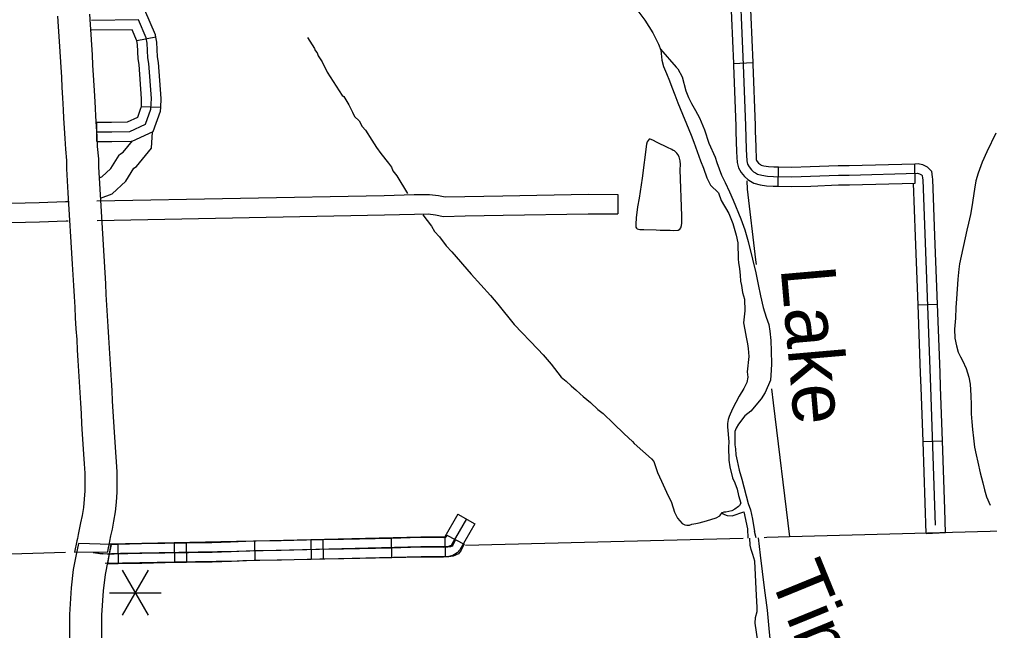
# Model space of a CAD drawing. Extents: x -117616 to 64730, y 54117 to 789866.
# Drawn here: x 62435.1 to 62585, y 55033 to 55127.3 of the extents above; entities that cross this region are included whole.
import ezdxf

# ---------------------------------------------------------------- set-up
doc = ezdxf.new("R2010")
doc.units = 0
for name, color, linetype in [('10', 7, 'Continuous'), ('2', 7, 'Continuous'), ('32', 7, 'Continuous'), ('35', 7, 'Continuous'), ('48', 7, 'Continuous'), ('Level 10', 7, 'Continuous'), ('Level 2', 7, 'Continuous'), ('Level 32', 7, 'Continuous'), ('Level 35', 7, 'Continuous'), ('Level 45', 7, 'Continuous'), ('Level 46', 7, 'Continuous'), ('Level 5', 7, 'Continuous')]:
    doc.layers.add(name, color=color, linetype=linetype)

msp = doc.modelspace()

# ---------------------------------------------------------------- linework, layer by layer
at = {"layer": '10'}
for points in [[(62444.23, 55046.37), (62443.89, 55044.71), (62443.44, 55042.37), (62443.12, 55039.56), (62442.84, 55035.45), (62442.87, 55033.31), (62442.86, 55030.92), (62443.07, 55026.85), (62443.12, 55024.64)], [(62448.12, 55024.76), (62448.06, 55027.03), (62447.86, 55031.04), (62447.87, 55033.33), (62447.84, 55035.32), (62448.1, 55039.1), (62448.39, 55041.61), (62448.8, 55043.74), (62449.28, 55046.24), (62444.23, 55046.37)]]:
    msp.add_lwpolyline(points, dxfattribs=at)
at = {"layer": '2'}
for points in [[(62654.83, 55050.09), (62554.1, 55047.4), (62550.56, 55047.3), (62550.19, 55047.29)], [(62546.95, 55047.18), (62504.02, 55046.07)]]:
    msp.add_lwpolyline(points, dxfattribs=at)
at = {"layer": '32'}
for p, q in [((62492.53, 55047.18), (62492.59, 55044.18)), ((62501.17, 55047.67), (62503.84, 55046.3)), ((62450.3, 55046.25), (62450.37, 55043.25)), ((62460.87, 55046.45), (62460.92, 55043.45)), ((62471.43, 55046.77), (62471.47, 55043.77)), ((62481.97, 55046.97), (62482.04, 55043.97))]:
    msp.add_line(p, q, dxfattribs=at)
for points in [[(62492.53, 55047.18), (62485.16, 55047.03), (62481.97, 55046.97)], [(62501.17, 55047.67), (62500.98, 55047.3), (62500.58, 55047.29), (62496.97, 55047.31), (62492.56, 55047.18), (62492.53, 55047.18)], [(62502.51, 55046.98), (62502.07, 55046.14), (62501.97, 55046), (62501.69, 55045.89), (62501.29, 55045.81), (62500.6, 55045.79), (62496.98, 55045.81), (62492.59, 55045.68), (62485.19, 55045.53), (62481.47, 55045.46), (62475.57, 55045.32), (62471.33, 55045.26), (62467.81, 55045.1), (62464.87, 55045.02), (62457.6, 55044.9), (62454.02, 55044.83), (62449.77, 55044.74), (62448.69, 55044.74), (62448.06, 55044.78), (62447.45, 55044.83), (62446.49, 55044.96)], [(62450.3, 55046.25), (62449.76, 55046.24), (62449.28, 55046.24), (62448.95, 55044.51), (62448.7, 55043.24)], [(62460.87, 55046.45), (62457.58, 55046.4), (62453.99, 55046.33), (62450.3, 55046.25)], [(62471.43, 55046.77), (62471.29, 55046.76), (62467.75, 55046.6), (62464.84, 55046.52), (62460.87, 55046.45)], [(62481.97, 55046.97), (62481.44, 55046.96), (62475.54, 55046.82), (62471.43, 55046.77)], [(62503.84, 55046.3), (62503.36, 55045.35), (62502.94, 55044.78), (62502.12, 55044.44), (62501.45, 55044.32), (62500.62, 55044.29), (62497, 55044.31), (62492.63, 55044.19), (62492.59, 55044.18)], [(62492.59, 55044.18), (62485.22, 55044.03), (62482.04, 55043.97)], [(62450.37, 55043.25), (62449.79, 55043.24), (62448.7, 55043.24)], [(62460.92, 55043.45), (62457.63, 55043.4), (62454.04, 55043.33), (62450.37, 55043.25)], [(62471.47, 55043.77), (62471.38, 55043.77), (62467.86, 55043.6), (62464.9, 55043.52), (62460.92, 55043.45)], [(62482.04, 55043.97), (62481.51, 55043.96), (62475.6, 55043.82), (62471.47, 55043.77)]]:
    msp.add_lwpolyline(points, dxfattribs=at)
at = {"layer": '35'}
for points in [[(62549.17, 55031.34), (62548.79, 55034.08), (62548.83, 55034.96), (62549.1, 55035.88), (62549.1, 55036.55), (62549, 55038.35), (62548.73, 55043.65), (62548.41, 55044.69), (62548.16, 55045.47), (62548, 55046.12), (62547.97, 55047.21)], [(62549.25, 55047.27), (62549.56, 55044.59), (62550.15, 55039.53), (62550.65, 55036.1), (62550.91, 55033.25), (62551.15, 55030.67)]]:
    msp.add_lwpolyline(points, dxfattribs=at)
at = {"layer": '48'}
for p, q in [((62455.01, 55042.26), (62451.01, 55035.34)), ((62451.01, 55042.26), (62455.01, 55035.34)), ((62449.01, 55038.8), (62457.01, 55038.8))]:
    msp.add_line(p, q, dxfattribs=at)
at = {"layer": 'Level 10'}
for p, q in [((62446.09, 55126.54), (62445.99, 55128.11)), ((62441, 55127.81), (62441.1, 55126.23)), ((62441.1, 55126.23), (62441.2, 55124.66)), ((62446.19, 55124.98), (62446.09, 55126.54)), ((62441.2, 55124.66), (62441.3, 55123.1)), ((62446.29, 55123.4), (62446.19, 55124.98)), ((62441.3, 55123.1), (62441.39, 55121.52)), ((62446.38, 55121.82), (62446.29, 55123.4)), ((62441.39, 55121.52), (62441.49, 55119.93)), ((62446.48, 55120.25), (62446.38, 55121.82)), ((62441.49, 55119.93), (62441.59, 55118.36)), ((62446.58, 55118.67), (62446.48, 55120.25)), ((62441.59, 55118.36), (62441.68, 55116.79)), ((62446.67, 55117.08), (62446.58, 55118.67)), ((62441.68, 55116.79), (62441.77, 55115.21)), ((62446.77, 55115.5), (62446.67, 55117.08)), ((62441.77, 55115.21), (62441.88, 55113.33)), ((62446.87, 55113.6), (62446.77, 55115.5)), ((62441.88, 55113.33), (62441.95, 55112.07)), ((62446.94, 55112.34), (62446.87, 55113.6)), ((62441.95, 55112.07), (62442.03, 55110.49)), ((62447.03, 55110.77), (62446.94, 55112.34)), ((62442.03, 55110.49), (62442.12, 55108.92)), ((62447.12, 55109.2), (62447.03, 55110.77)), ((62442.12, 55108.92), (62442.21, 55107.29)), ((62447.2, 55107.67), (62447.12, 55109.2)), ((62442.21, 55107.29), (62442.38, 55105.53)), ((62447.38, 55105.77), (62447.2, 55107.67)), ((62447.38, 55104.53), (62447.38, 55105.77)), ((62442.38, 55105.53), (62442.38, 55104.22)), ((62442.38, 55104.22), (62442.58, 55100.55)), ((62448.44, 55086.49), (62447.38, 55104.53)), ((62442.58, 55100.55), (62443.26, 55089.53)), ((62443.26, 55089.53), (62443.35, 55087.87)), ((62443.35, 55087.87), (62443.45, 55086.2)), ((62443.45, 55086.2), (62443.55, 55084.54)), ((62448.54, 55084.83), (62448.44, 55086.49)), ((62448.64, 55083.18), (62448.54, 55084.83)), ((62443.55, 55084.54), (62443.65, 55082.88)), ((62448.74, 55081.52), (62448.64, 55083.18)), ((62443.65, 55082.88), (62443.75, 55081.21)), ((62443.75, 55081.21), (62443.85, 55079.55)), ((62448.84, 55079.87), (62448.74, 55081.52)), ((62443.85, 55079.55), (62443.96, 55077.91)), ((62448.95, 55078.21), (62448.84, 55079.87)), ((62443.96, 55077.91), (62444.06, 55076.26)), ((62449.05, 55076.55), (62448.95, 55078.21)), ((62444.06, 55076.26), (62444.15, 55074.62)), ((62449.14, 55074.9), (62449.05, 55076.55)), ((62444.15, 55074.62), (62444.24, 55072.98)), ((62449.23, 55073.25), (62449.14, 55074.9)), ((62444.24, 55072.98), (62444.33, 55071.34)), ((62449.32, 55071.62), (62449.23, 55073.25)), ((62444.33, 55071.34), (62444.43, 55069.7)), ((62449.42, 55070.01), (62449.32, 55071.62)), ((62444.43, 55069.7), (62444.53, 55068.08)), ((62449.52, 55068.39), (62449.42, 55070.01)), ((62449.62, 55066.78), (62449.52, 55068.39)), ((62444.53, 55068.08), (62444.63, 55066.47)), ((62449.72, 55065.17), (62449.62, 55066.78)), ((62444.63, 55066.47), (62444.73, 55064.87)), ((62449.81, 55063.59), (62449.72, 55065.17)), ((62444.73, 55064.87), (62444.82, 55063.29)), ((62444.82, 55063.29), (62444.92, 55061.72)), ((62449.91, 55062.03), (62449.81, 55063.59)), ((62444.92, 55061.72), (62445.02, 55060.18)), ((62450.01, 55060.5), (62449.91, 55062.03)), ((62445.02, 55060.18), (62445.11, 55058.68)), ((62450.1, 55058.98), (62450.01, 55060.5)), ((62445.11, 55058.68), (62445.2, 55057.23)), ((62450.19, 55057.45), (62450.1, 55058.98)), ((62445.2, 55057.23), (62445.24, 55055.85)), ((62450.24, 55055.89), (62450.19, 55057.45)), ((62445.24, 55055.85), (62445.22, 55054.52)), ((62450.22, 55054.33), (62450.24, 55055.89)), ((62445.14, 55053.23), (62444.99, 55051.97)), ((62445.22, 55054.52), (62445.14, 55053.23)), ((62450.12, 55052.78), (62450.22, 55054.33)), ((62444.99, 55051.97), (62444.79, 55050.74)), ((62449.94, 55051.28), (62450.12, 55052.78)), ((62444.79, 55050.74), (62444.57, 55049.59)), ((62449.71, 55049.86), (62449.94, 55051.28)), ((62444.57, 55049.59), (62444.36, 55048.58)), ((62449.47, 55048.62), (62449.71, 55049.86)), ((62444.08, 55047.18), (62443.99, 55046.79)), ((62444.2, 55047.77), (62444.08, 55047.18)), ((62444.36, 55048.58), (62444.2, 55047.77)), ((62449.09, 55046.76), (62449.26, 55047.58)), ((62449.26, 55047.58), (62449.47, 55048.62)), ((62443.99, 55046.79), (62443.62, 55045.05)), ((62448.75, 55045.12), (62448.88, 55045.76)), ((62448.88, 55045.76), (62448.97, 55046.16)), ((62448.97, 55046.16), (62449.09, 55046.76)), ((62443.62, 55045.05), (62448.75, 55045.12))]:
    msp.add_line(p, q, dxfattribs=at)
at = {"layer": 'Level 2'}
msp.add_lwpolyline([(62442.23, 55045.01), (62351.19, 55042.23)], dxfattribs=at)
at = {"layer": 'Level 32'}
for p, q in [((62456.21, 55124.58), (62453.26, 55123.99)), ((62456.95, 55113.7), (62453.95, 55113.83)), ((62447.07, 55108.46), (62447.07, 55111.46))]:
    msp.add_line(p, q, dxfattribs=at)
for points in [[(62456.21, 55124.58), (62456.14, 55124.9), (62454.51, 55128.72), (62446.22, 55128.62)], [(62447.07, 55109.96), (62449.37, 55109.96), (62452.17, 55110.02), (62454.59, 55111.12), (62455.43, 55113.43), (62455.5, 55115.07), (62455.09, 55120.49), (62454.95, 55121.39), (62454.87, 55123.62), (62454.7, 55124.45), (62453.52, 55127.21), (62446.23, 55127.12)], [(62453.26, 55123.99), (62453.26, 55124), (62452.54, 55125.69), (62446.25, 55125.62)], [(62453.95, 55113.83), (62454, 55115.04), (62453.6, 55120.32), (62453.45, 55121.24), (62453.37, 55123.45), (62453.26, 55123.99)], [(62456.95, 55113.7), (62457.01, 55115.09), (62456.58, 55120.67), (62456.44, 55121.53), (62456.36, 55123.8), (62456.21, 55124.58)], [(62447.07, 55111.46), (62449.35, 55111.46), (62451.83, 55111.51), (62453.4, 55112.22), (62453.94, 55113.73), (62453.95, 55113.83)], [(62447.07, 55108.46), (62449.38, 55108.46), (62452.51, 55108.52), (62455.79, 55110.01), (62456.92, 55113.14), (62456.95, 55113.7)]]:
    msp.add_lwpolyline(points, dxfattribs=at)
at = {"layer": 'Level 35'}
for points in [[(62530.19, 55129.24), (62531.73, 55127.16), (62532.97, 55125.25)], [(62532.97, 55125.25), (62533.84, 55123.48), (62534.23, 55122.54), (62534.38, 55121), (62534.61, 55120.03), (62535.09, 55118.95), (62535.54, 55117.83), (62535.93, 55116.84), (62536.38, 55115.64), (62536.82, 55114.44), (62538.91, 55109.42), (62539.3, 55108.34), (62540.33, 55105.48), (62540.79, 55104.32), (62541.3, 55102.86), (62541.86, 55101.7), (62543.12, 55100.52), (62543.54, 55099.34), (62544.72, 55097.32), (62545.31, 55095.8), (62545.85, 55093.97), (62546.09, 55092.83), (62546.16, 55090.29), (62546.23, 55089.79), (62546.37, 55088.78), (62546.48, 55087.83), (62546.51, 55086.91), (62546.65, 55086.21), (62546.83, 55085.15), (62547.14, 55084.13), (62547.21, 55082.3), (62546.96, 55080.47), (62547.21, 55079.37), (62547.41, 55078.24), (62547.58, 55077.2), (62547.7, 55076.49), (62547.8, 55075.25), (62547.56, 55072.9), (62547.67, 55072.09), (62547.49, 55071.26), (62547.03, 55070.32), (62546.3, 55069.13), (62545.27, 55067.19), (62544.77, 55065.98), (62544.63, 55065.54), (62544.53, 55064.93), (62544.52, 55064.4), (62544.73, 55062.08), (62544.65, 55061.25), (62544.71, 55059.25), (62544.89, 55058.23), (62545.28, 55056.54), (62545.62, 55055.77), (62545.99, 55054.8), (62546.21, 55053.82), (62546.58, 55052.63), (62546.38, 55052.25), (62546.21, 55052.09), (62545.64, 55051.68), (62545.2, 55051.44), (62544.27, 55051.25), (62544.05, 55051.23), (62543.94, 55051.23), (62543.66, 55051.15), (62543.81, 55050.98), (62544.48, 55050.74), (62545.21, 55050.69), (62547.05, 55051.28), (62547.62, 55048.66), (62547.66, 55047.2)], [(62479.61, 55124.5), (62480.36, 55123.37), (62480.7, 55122.82), (62480.78, 55122.48), (62481.1, 55122.12), (62481.29, 55121.69), (62481.88, 55120.75), (62482.66, 55119.15), (62484.98, 55115.55), (62485.21, 55115.38), (62485.72, 55114.61), (62486.01, 55114.1), (62486.55, 55112.97), (62486.88, 55112.31), (62487.58, 55111.62), (62488.08, 55110.79), (62488.6, 55110.19), (62489.58, 55108.66), (62490.3, 55107.52), (62490.96, 55106.59), (62492.14, 55105.13), (62492.61, 55104.47), (62492.81, 55103.92), (62493.42, 55103.14), (62495.09, 55100.45)], [(62534.16, 55122.71), (62536.6, 55119.95), (62536.83, 55119.68), (62537.49, 55118.43), (62538.08, 55116.25), (62538.47, 55115.26), (62538.94, 55114.34), (62539.56, 55113.23), (62540.19, 55112.1), (62540.95, 55110.23), (62541.61, 55108.19), (62542.62, 55106.02), (62542.88, 55105.19), (62543.56, 55103.25), (62544.14, 55102.12), (62544.79, 55100.66), (62545.38, 55099.39), (62546.58, 55096.54), (62547.17, 55094.82), (62547.68, 55093.04), (62548.37, 55090.29), (62548.9, 55088.16), (62549.26, 55086.37), (62549.61, 55084.65), (62550.04, 55082.84), (62550.48, 55081.32), (62550.89, 55080.2), (62551.04, 55079.19), (62551.19, 55077.73), (62551.26, 55076.09), (62551.28, 55074.12), (62551.25, 55073.13), (62551.14, 55071.62), (62550.32, 55069.69), (62549.71, 55068.74), (62548.09, 55066.81), (62547.19, 55066.11), (62546.19, 55064.8), (62545.82, 55064.22), (62545.63, 55063.71), (62545.63, 55062.48), (62545.63, 55062.06), (62545.65, 55061.62), (62545.72, 55061), (62545.77, 55060.07), (62545.98, 55059.16), (62546.3, 55057.72), (62546.71, 55056.34), (62547.69, 55052.55), (62548.04, 55051.59), (62548.37, 55050.16), (62548.7, 55048.27)], [(62537.44, 55095.86), (62537.47, 55096.99), (62537.18, 55104.09), (62537.23, 55104.92), (62537.19, 55105.48), (62537.05, 55106.09), (62536.85, 55106.46), (62536.69, 55106.66), (62536.52, 55106.83), (62536.32, 55107), (62536.13, 55107.08), (62535.89, 55107.22), (62535.23, 55107.54), (62533.66, 55108.32), (62532.98, 55108.64), (62532.56, 55108.82), (62532.42, 55108.8), (62532.09, 55108.39), (62532, 55108.03), (62531.32, 55102.78), (62530.85, 55099.72), (62530.62, 55098.38), (62530.41, 55096.69), (62530.37, 55095.71), (62530.35, 55095.33), (62530.35, 55095.21), (62530.44, 55095.06), (62530.57, 55094.98), (62530.97, 55094.88), (62531.58, 55094.86), (62533.51, 55094.8), (62534.08, 55094.78), (62534.5, 55094.78), (62534.98, 55094.75), (62535.45, 55094.74), (62535.66, 55094.74), (62536.16, 55094.73), (62536.89, 55094.78), (62537.12, 55094.91), (62537.3, 55095.12), (62537.4, 55095.48), (62537.44, 55095.86)], [(62585.98, 55109.73), (62584.57, 55106.85), (62583.83, 55105.26), (62583.23, 55103.57), (62582.89, 55102.38), (62582.68, 55101.09), (62582.24, 55098.37), (62582.04, 55097.16), (62581.75, 55095.84), (62581.48, 55094.74), (62580.37, 55089.56), (62580.27, 55088.75), (62580.11, 55087.18), (62579.88, 55084.15), (62579.79, 55082.82), (62579.73, 55081.19), (62579.6, 55079.5), (62579.65, 55078.11), (62579.89, 55076.92), (62580.14, 55075.95), (62580.49, 55075.23), (62580.82, 55074.64), (62581.4, 55073.42), (62581.79, 55072.06), (62581.99, 55070.98), (62582.12, 55069.22), (62582.15, 55067.78), (62582.14, 55066.43), (62582.24, 55065.17), (62582.34, 55063.99), (62582.51, 55062.65), (62582.68, 55061.26), (62582.9, 55060.08), (62583.16, 55058.93), (62583.56, 55057.3), (62583.94, 55055.78), (62584.19, 55054.69), (62584.53, 55053.6), (62585.1, 55052.33)], [(62497.43, 55097.15), (62498.77, 55095.37), (62499.25, 55094.58), (62499.99, 55093.76), (62501.06, 55092.37), (62501.91, 55091.43), (62504.91, 55087.98), (62507.87, 55084.66), (62509, 55083.33), (62511.56, 55080.19), (62515.23, 55076.42), (62516.05, 55075.54), (62517.25, 55074.09), (62518.79, 55072.09), (62519.57, 55071.48), (62520.35, 55070.76), (62520.75, 55070.4), (62521.07, 55070.14), (62521.76, 55069.52), (62522.2, 55069.07), (62523.33, 55068.14), (62524.47, 55067.08), (62525.32, 55066.44), (62526.9, 55064.9), (62528.52, 55063.33), (62529.82, 55062.15), (62530.11, 55061.82), (62532.77, 55059.46), (62533.1, 55059.03), (62533.71, 55057.37), (62534.31, 55056.02), (62535.06, 55054.3), (62535.83, 55052.71), (62536.33, 55051.24), (62536.79, 55050.33), (62537.52, 55049.5), (62537.91, 55049.28), (62538.2, 55049.23), (62538.66, 55049.25), (62539, 55049.37), (62539.6, 55049.5), (62540.13, 55049.59)], [(62540.13, 55049.59), (62541.24, 55049.87), (62542.78, 55050.35), (62543.34, 55050.69), (62543.67, 55051.16)], [(62548.92, 55047.25), (62548.7, 55048.27)]]:
    msp.add_lwpolyline(points, dxfattribs=at)
at = {"layer": 'Level 45'}
for p, q in [((62545.41, 55120.5), (62548.4, 55120.63)), ((62552.34, 55101.55), (62552.4, 55104.55)), ((62573.52, 55102.03), (62573.44, 55105.03)), ((62573.89, 55083.24), (62576.89, 55083.35)), ((62574.66, 55062.13), (62577.66, 55062.24)), ((62502.87, 55050.93), (62505.47, 55049.43)), ((62500.84, 55047.4), (62500.87, 55044.4)), ((62575.2, 55047.96), (62578.2, 55048.07)), ((62459.01, 55046.5), (62459.07, 55043.5)), ((62480.12, 55046.95), (62480.19, 55043.95))]:
    msp.add_line(p, q, dxfattribs=at)
for points in [[(62546.25, 55136.19), (62546.92, 55120.31), (62547.27, 55110.86), (62547.38, 55107.29), (62547.4, 55107.24), (62547.47, 55105.46), (62547.62, 55104.94), (62547.85, 55104.52), (62548.21, 55104.08), (62548.53, 55103.79), (62548.83, 55103.6), (62549.15, 55103.41), (62549.83, 55103.24), (62550.7, 55103.11), (62551.63, 55103.07), (62554.47, 55103.01), (62557.32, 55103.08), (62561.65, 55103.26), (62563.32, 55103.26), (62573.84, 55103.54), (62574.15, 55103.48), (62574.46, 55103.32), (62574.59, 55103.19), (62574.64, 55102.78), (62574.66, 55102.54), (62575.87, 55070.52), (62576.6, 55049.22)], [(62547.96, 55131.18), (62548.4, 55120.63)], [(62544.96, 55131.05), (62545.41, 55120.5)], [(62548.4, 55120.63), (62548.41, 55120.37), (62548.77, 55110.91), (62548.8, 55110.06)], [(62545.41, 55120.5), (62545.42, 55120.25), (62545.77, 55110.81), (62545.8, 55109.96)], [(62545.8, 55109.96), (62545.89, 55106.91), (62545.92, 55106.87), (62545.98, 55105.22), (62546.22, 55104.37), (62546.6, 55103.68), (62547.12, 55103.03), (62547.63, 55102.59), (62548.04, 55102.33), (62548.57, 55102.01), (62549.53, 55101.77), (62550.55, 55101.62), (62551.58, 55101.57), (62552.34, 55101.55)], [(62548.8, 55110.06), (62548.87, 55107.66), (62548.89, 55107.62), (62548.96, 55105.7), (62549.01, 55105.52), (62549.1, 55105.36), (62549.29, 55105.12), (62549.44, 55105), (62549.62, 55104.88), (62549.73, 55104.81), (62550.12, 55104.71), (62550.84, 55104.6), (62551.68, 55104.56), (62552.4, 55104.55)], [(62552.4, 55104.55), (62554.46, 55104.51), (62557.27, 55104.58), (62561.62, 55104.76), (62562.93, 55104.76)], [(62562.93, 55104.76), (62563.3, 55104.76), (62573.44, 55105.03)], [(62573.44, 55105.03), (62573.98, 55105.05), (62574.65, 55104.9), (62575.35, 55104.55), (62576.03, 55103.87), (62576.13, 55102.93), (62576.16, 55102.63), (62576.49, 55093.9)], [(62552.34, 55101.55), (62554.47, 55101.51), (62557.37, 55101.58), (62561.68, 55101.76), (62562.93, 55101.76)], [(62562.93, 55101.76), (62563.34, 55101.76), (62573.52, 55102.03)], [(62573.18, 55102.03), (62573.49, 55093.79)], [(62573.49, 55093.79), (62573.89, 55083.24)], [(62576.49, 55093.9), (62576.89, 55083.35)], [(62573.89, 55083.24), (62574.29, 55072.68)], [(62576.89, 55083.35), (62577.29, 55072.8)], [(62574.29, 55072.68), (62574.37, 55070.47), (62574.66, 55062.13)], [(62577.29, 55072.8), (62577.37, 55070.58), (62577.66, 55062.24)], [(62577.66, 55062.24), (62578.02, 55051.68)], [(62574.66, 55062.13), (62575.14, 55047.96)], [(62578.02, 55051.68), (62578.14, 55048.04)], [(62502.87, 55050.93), (62500.84, 55047.4)], [(62504.17, 55050.18), (62501.93, 55046.29), (62501.79, 55046.11), (62501.53, 55045.97), (62501.27, 55045.9)], [(62505.47, 55049.43), (62503.17, 55045.43), (62502.76, 55044.94), (62502.09, 55044.56), (62501.47, 55044.4)], [(62490.68, 55047.2), (62480.12, 55046.95)], [(62500.84, 55047.4), (62497.11, 55047.36), (62490.68, 55047.2)], [(62501.27, 55045.9), (62497.14, 55045.86), (62468.7, 55045.18), (62450.73, 55044.84), (62447.88, 55044.77), (62446.52, 55044.98)], [(62459.01, 55046.5), (62449, 55046.31)], [(62469.56, 55046.7), (62468.67, 55046.68), (62459.01, 55046.5)], [(62480.12, 55046.95), (62469.56, 55046.7)], [(62490.75, 55044.2), (62480.19, 55043.95)], [(62501.47, 55044.4), (62497.17, 55044.36), (62490.75, 55044.2)], [(62459.07, 55043.5), (62448.36, 55043.3)], [(62469.63, 55043.7), (62468.73, 55043.68), (62459.07, 55043.5)], [(62480.19, 55043.95), (62469.63, 55043.7)]]:
    msp.add_lwpolyline(points, dxfattribs=at)
at = {"layer": 'Level 46'}
for points in [[(62447.64, 55099.72), (62449.45, 55100.4), (62451.55, 55102.35), (62452.81, 55104.34), (62453.18, 55104.6), (62455.51, 55107.4), (62455.65, 55109.95)], [(62447.46, 55102.86), (62447.84, 55103), (62449.22, 55104.28), (62450.53, 55106.35), (62450.57, 55106.44), (62451.14, 55106.83), (62452.56, 55108.55)], [(62447.05, 55099.28), (62491.46, 55100.13), (62496.11, 55100.26), (62498.45, 55100.28), (62499.86, 55100.11), (62500.89, 55099.89), (62503.91, 55099.96), (62509.8, 55100.09), (62522.96, 55100.31), (62527.57, 55100.28)], [(62527.57, 55100.28), (62527.55, 55097.28)], [(62347.42, 55096.91), (62352.18, 55096.99), (62361.38, 55097.19), (62367.87, 55097.41), (62375.4, 55097.6), (62386.68, 55097.83), (62386.89, 55097.84), (62396.42, 55098.14), (62400.85, 55098.14), (62413.52, 55098.47), (62427.36, 55098.77), (62438.15, 55099.04), (62442.24, 55099.19), (62442.61, 55099.2)], [(62447.1, 55096.28), (62491.53, 55097.13), (62496.17, 55097.26), (62498.28, 55097.28), (62499.37, 55097.14), (62500.62, 55096.88), (62503.98, 55096.96), (62509.86, 55097.09), (62522.97, 55097.31), (62527.55, 55097.28)], [(62388.05, 55094.88), (62396.47, 55095.14), (62400.89, 55095.14), (62413.59, 55095.47), (62427.43, 55095.77), (62438.24, 55096.04), (62442.32, 55096.19), (62442.67, 55096.2)]]:
    msp.add_lwpolyline(points, dxfattribs=at)
at = {"layer": 'Level 5'}
for points in [[(62547.51, 55102.37), (62547.56, 55101.11), (62548.85, 55090.19), (62548.94, 55089.47)], [(62551.28, 55070.28), (62551.54, 55068.13), (62554.1, 55047.4)]]:
    msp.add_lwpolyline(points, dxfattribs=at)

# ---------------------------------------------------------------- texts
at = {"layer": '35'}
msp.add_text('Timber', height=8.448, rotation=292.2284, dxfattribs=at).set_placement((62550.88, 55041.49))
at = {"layer": 'Level 35'}
msp.add_text('Lake', height=8.448, rotation=274.9721, dxfattribs=at).set_placement((62552.71, 55088.9))

doc.saveas('drawing.dxf')
